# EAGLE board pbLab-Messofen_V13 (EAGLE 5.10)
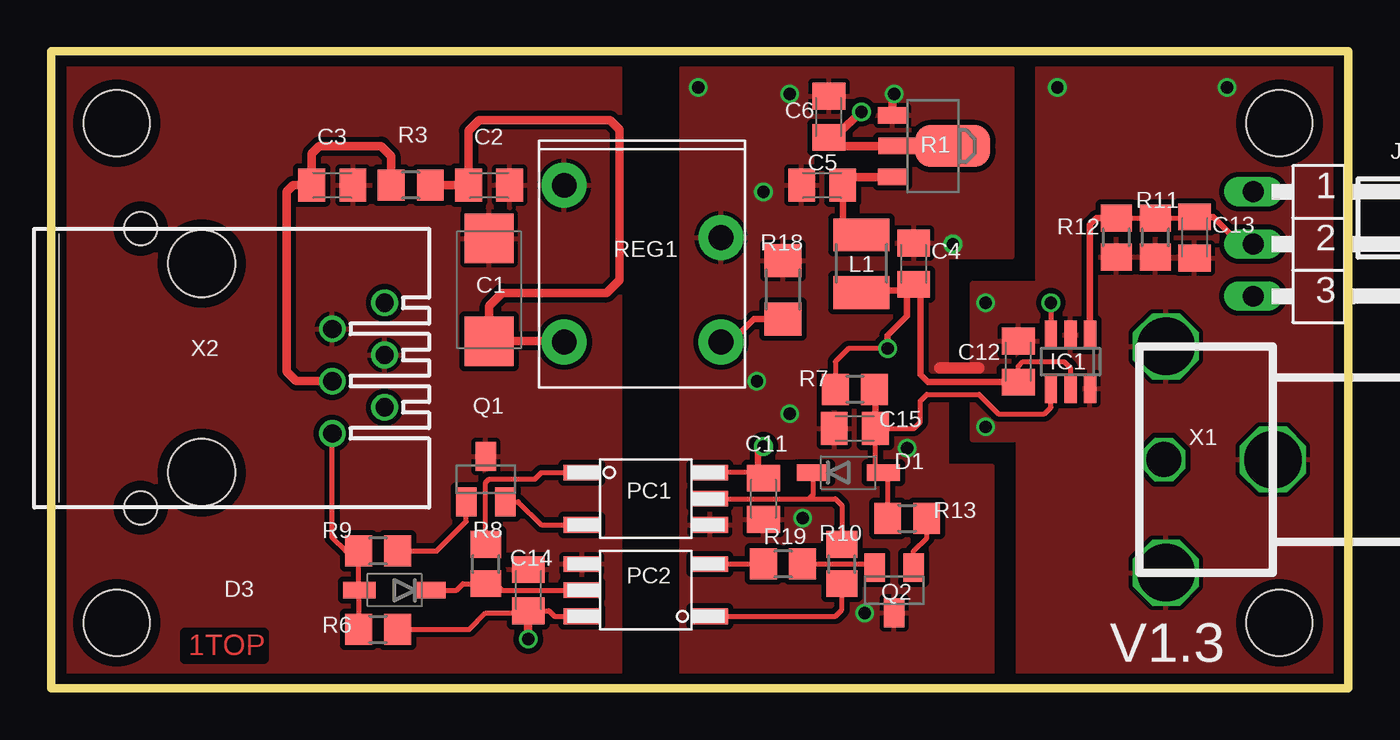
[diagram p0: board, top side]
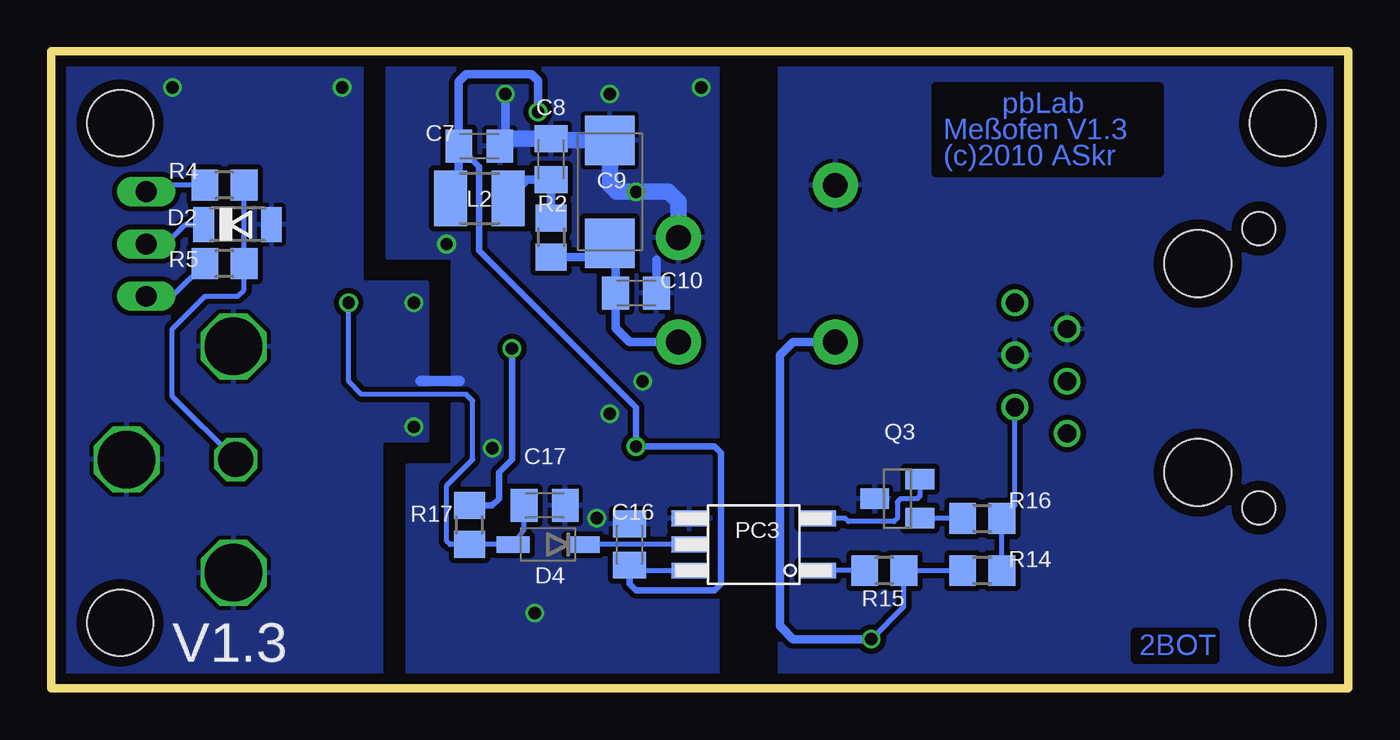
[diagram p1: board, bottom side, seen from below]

Size 63.02 x 30.96 mm. Coordinates in mm from the lower left corner, seen from the top.
Outline: 63.02,30.96 0,30.96 0,0 63.02,0 63.02,30.96
Copper layers (1*16): Top 0.035mm / dielectric 1.5mm / Bottom 0.035mm
Design rules "pcb-pool-2009": minimum track width 6mil, minimum drill 12mil, track to track 6mil, track to pad 6mil, pad to pad 6mil, via to via 6mil, smd to smd 6mil, copper to edge 20mil, drill to drill 8mil, minimum pad ring 8mil, minimum via ring 6mil, stop-mask expansion 3mil, vias tented up to drill 0mil, thermal gap 8mil
Holes 3.2 mm at 3.17,27.46 3.17,3.17 59.69,3.17 59.69,27.46
tRestrict: 8 lines
bRestrict: 8 lines

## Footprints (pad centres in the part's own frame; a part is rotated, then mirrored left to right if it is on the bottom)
SMC_C = smd 2.4 x 2.4: + -2.5,0; - 2.5,0
C0805K = smd 1.3 x 1.6: 1 -1,0; 2 1,0
SOD123 = smd 1.6 x 0.8: A 1.7,0; C -1.7,0
SOD80-R = smd 1 x 1.7: A 1.65,0; C -1.65,0
AKKI_SOT236W = smd 0.6 x 1.4: 1 -0.95,-1.303; 2 0,-1.303; 3 0.95,-1.303; 4 0.95,1.303; 5 0,1.303; 6 -0.95,1.303
1X03/90 = drill 1.016 long: 1 -2.54,-3.81; 2 0,-3.81; 3 2.54,-3.81
R1210 = smd 1.6 x 2.7: 1 -1.4,0; 2 1.4,0
AKKI_OPTOCOUP6SMD = smd 1.778 x 0.762: 1 -3.111,1.27; 3 -3.111,-1.27; 4 3.111,-1.27; 5 3.111,0; 6 3.111,1.27
SOT23-BEC = smd 1 x 1.4: B -0.95,-1.1; C 0,1.1; E 0.95,-1.1
SOT89 = smd 0.8 x 1.4: 1 -1.499,-1.981; 3 1.499,-1.981 | smd 0.8 x 1.9: 2 0,-1.727 | smd 2.032 x 3.65: 2@1 0,0.94
R0805 = smd 1.3 x 1.5: 1 -0.95,0; 2 0.95,0
R1206 = smd 1.6 x 1.803: 1 -1.422,0; 2 1.422,0
AKKI_AM1P-Z = drill 1.2 pad 2.184 round: 1 -2.54,-5.08; 4 5.08,-5.08; 5 5.08,2.54; 7 0,2.54
AKKI_CHINCH_CBP5 = drill 2.8 octagon: 1-1 5.2,-5.5; 1-2 5.2,5.5; 1-3 0,0 | drill 1.7 octagon: 2 5.3,0
AKKI_MEBP6-6G = drill 0.889 round: 1 -3.175,7.62; 2 -1.905,5.08; 3 -0.635,7.62; 4 0.635,5.08; 5 1.905,7.62; 6 3.175,5.08 | hole 3.251: -5.08,-1.27; 5.08,-1.27 | hole 1.6: -6.785,-4.24; 6.785,-4.24

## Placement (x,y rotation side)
C1  10u;16V  [SMC_C]  21.27,19.37 90 top
C2  100n  [C0805K]  21.27,24.45 0 top
C3  100n  [C0805K]  13.65,24.45 0 top
C4  1u  [C0805K]  41.91,20.64 90 top
C5  100n  [C0805K]  37.47,24.45 180 top
C6  10u  [C0805K]  37.78,27.78 90 top
C7  100n  [C0805K]  42.23,26.35 0 bottom
C8  100n  [C0805K]  38.73,25.72 90 bottom
C9  10u;16V  [SMC_C]  35.88,24.13 90 bottom
C10  100n  [C0805K]  34.61,19.21 0 bottom
C11  470n  [C0805K]  34.61,9.21 90 top
C12  100n  [C0805K]  46.99,15.88 90 top
C13  100n  [C0805K]  55.56,21.91 270 top
C14  470n  [C0805K]  23.18,4.76 90 top
C15  22p  [C0805K]  39.05,12.62 180 top
C16  470n  [C0805K]  34.92,6.99 270 bottom
C17  22p  [C0805K]  39.05,8.89 0 bottom
D1  LL103  [SOD123]  38.73,10.48 0 top
D2  4V7  [SOD80-R]  53.98,22.54 0 bottom
D3  LL103  [SOD123]  16.67,4.76 180 top
D4  LL103  [SOD123]  38.89,6.99 180 bottom
IC1  MCP3421  [AKKI_SOT236W]  49.53,15.88 180 top
JP1  [1X03/90]  62.23,21.59 270 top
L1  10u  [R1210]  39.37,20.64 90 top
L2  10u  [R1210]  42.23,23.81 0 bottom
PC1  TLP102  [AKKI_OPTOCOUP6SMD]  28.89,9.21 0 top
PC2  TLP102  [AKKI_OPTOCOUP6SMD]  28.89,4.76 180 top
PC3  TLP102  [AKKI_OPTOCOUP6SMD]  28.89,6.99 180 bottom
Q1  BC807-40  [SOT23-BEC]  21.11,10.16 0 top
Q2  BC807-40  [SOT23-BEC]  40.96,4.76 180 top
Q3  BC807-40  [SOT23-BEC]  21.91,9.21 90 bottom
R1  S817B33  [SOT89]  42.86,26.35 270 top
R2  10E  [R0805]  38.73,21.91 270 bottom
R3  1E  [R0805]  17.46,24.45 180 top
R4  1M2  [R0805]  54.61,24.45 180 bottom
R5  5k6  [R0805]  54.61,20.64 180 bottom
R6  120k  [R0805]  15.88,2.86 0 top
R7  120k  [R0805]  39.05,14.53 180 top
R8  470E  [R0805]  21.11,6.03 90 top
R9  5k6  [R0805]  15.88,6.67 180 top
R10  470E  [R0805]  38.42,6.03 90 top
R11  120k  [R0805]  53.66,21.91 90 top
R12  120k  [R0805]  51.75,21.91 90 top
R13  5k6  [R0805]  41.59,8.26 0 top
R14  120k  [R0805]  17.78,5.71 180 bottom
R15  680E  [R0805]  22.54,5.72 180 bottom
R16  5k6  [R0805]  17.78,8.26 0 bottom
R17  120k  [R0805]  42.7,7.94 90 bottom
R18  470E  [R1206]  35.56,19.37 270 top
R19  0E  [R0805]  35.56,6.03 180 top
REG1  AM1P-Z  [AKKI_AM1P-Z]  30,21.91 270 top
X1  CHINCH  [AKKI_CHINCH_CBP5]  59.37,11.11 180 top
X2  MEBP6-6G  [AKKI_MEBP6-6G]  8.57,15.56 270 top

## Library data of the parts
C1 C9 = rcl; SMDPAC: SMCC
C2-C8 C10-C17 R2-R17 R19 = rcl; SMDPAC: 0805
D1 D3 D4 = Akki; SMDPAC: SOD123
D2 = Akki; SMDPAC: SOD80
IC1 PC1-PC3 R1 REG1 X1 X2 = Akki
JP1 = pinhead
L1 L2 = Akki; SMDPAC: 1210
Q1-Q3 = transistor-pnp
R18 = rcl

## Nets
+3V3: C4.1 C12.1 IC1.5 L1.1 R7.2 R17.2
+5V: C3.1 R3.2 X2.4
+UB: C6.1 C7.1 C11.2 C16.2 L2.1 PC1.6 PC3.6 R1.2
+UB#2: C1.+ C2.1 C14.1 PC2.6 R3.1 R6.2 R14.2 R15.1 REG1.4
GNDI: C1.- C2.2 C3.2 C14.2 PC2.4 Q1.C Q3.C REG1.1 X2.2 X2.3
GNDO: C4.2 C5.2 C6.2 C7.2 C8.2 C9.- C10.2 C11.1 C12.2 C13.2 C15.2 C16.1 C17.2 D2.A IC1.2 IC1.6 PC1.4 PC3.4 Q2.C R1.1 R11.1 R12.1 R18.1 REG1.7 X1.1-1 X1.1-2 X1.1-3
N$1: PC3.3 Q3.E
N$2: C8.1 L2.2 R2.1
N$3: C9.+ C10.1 R2.2 R18.2 REG1.5
N$4: C5.1 L1.2 R1.3
N$5: PC3.1 R15.2
N$6: JP1.1 R4.2
N$7: Q3.B R16.1
N$8: R14.1 R16.2 X2.5
N$9: JP1.3 R5.2
N$10: C13.1 D2.C IC1.1 JP1.2 R11.2 R12.2
N$11: D4.C PC3.5
N$12: PC2.3 R19.2
N$13: R4.1 R5.1 X1.2
N$14: Q2.E R19.1
N$17: PC1.1 R8.2
N$18: D3.C PC2.5 R8.1
N$19: PC1.3 Q1.E
N$20: Q1.B R9.1
N$21: D3.A R6.1 R9.2 X2.6
N$22: PC2.1 R10.1
N$24: Q2.B R13.2
N$26: D1.C PC1.5 R10.2
SCL: C17.1 D4.A IC1.3 R17.1
SDA: C15.1 D1.A IC1.4 R7.1 R13.1

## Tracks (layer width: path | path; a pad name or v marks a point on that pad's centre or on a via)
+3V3  (via drill 0.6)
  Top 0.254: IC1.5 49.53,15.56 49.21,15.88 47.23,15.88 46.99,15.64 C12.1 | R7.2 38.1,15.88 38.73,16.51 v40.64,16.51
  Top 0.305: C12.1 42.59,14.88 42.23,15.24 42.23,19 C4.1 41.59,19.32 | v40.64,16.51 40.64,17.14 41.59,18.1 41.59,19.32 | 41.59,19.32 39.45,19.32 L1.1
  Bottom 0.305: v40.64,16.51 40.64,11.11 41.27,10.48 41.27,9.21 41.59,8.89 R17.2
+5V
  Top 0.406: X2.4 11.91,14.92 11.43,15.4 11.43,24.13 11.75,24.45 C3.1 | C3.1 | C3.1 12.65,25.99 13.02,26.35 16.03,26.35 16.51,25.88 R3.2
+UB  (via drill 0.6)
  Top 0.254: PC1.6 34.34,10.48 C11.2
  Top 0.305: 34.34,10.48 34.34,11.48 v34.61,11.75 | 38.21,26.94 C6.1
  Top 0.406: v39.37,28.02 38.21,26.94 | R1.2 38.37,26.35 C6.1
  Bottom 0.254: PC3.6 34.66,5.71 C16.2
  Bottom 0.305: C16.2 34.92,5.08 34.61,4.76 30.8,4.76 30.48,5.08 30.48,11.43 30.8,11.75 v34.61,11.75 34.61,13.65 42.23,21.27 42.23,25.35 C7.1
  Bottom 0.406: L2.1 43.23,24.21 C7.1 43.23,29.48 42.86,29.84 39.69,29.84 39.37,29.53 v39.37,28.02
+UB#2  (via drill 0.6)
  Top 0.254: PC2.6 24.45,3.49 24.18,3.76 C14.1 | C14.1 23.13,3.81 | R6.2 20.32,2.86 21.11,3.65 23.07,3.65 C14.1
  Top 0.406: REG1.4 24.88,16.87 C1.+ 21.27,18.57 21.91,19.21 26.99,19.21 27.62,19.84 27.62,27.15 27.15,27.62 20.8,27.62 20.27,27.1 C2.1 R3.1 | C14.1 v23.18,2.38
  Bottom 0.254: R14.2 R15.1 21.59,3.97 v23.18,2.38
  Bottom 0.406: REG1.4 26.99,16.83 27.62,16.19 27.62,3.02 26.99,2.38 v23.18,2.38
GNDI
  pour Top (isolate 0.254): 0.64,30.16 27.62,30.16 27.62,0.32 0.64,0.32
  pour Bottom (isolate 0.254): 0.64,30.16 27.62,30.16 27.62,0.32 0.64,0.32
GNDO  (via drill 0.6)
  Top 0.406: R1.1 40.88,28.82 v40.96,28.89 40.91,28.94 | C6.2 37.73,28.89
  Top 0.559: 45.09,15.56 43.18,15.56
  Bottom 0.406: C10.2 33.61,20.84 | v40.96,28.89 40.96,26.62 C7.2
  Bottom 0.508: 43.18,14.92 45.09,14.92
  Bottom 0.813: REG1.7 32.54,23.65 33.02,24.13 35.56,24.13 35.88,24.45 C9.- 38.65,26.63 C8.2 40.86,26.72 C7.2
  other vias: 43.81,21.59 48.9,29.21 57.15,29.21 45.4,12.7 45.4,18.73 31.43,29.21 35.88,28.89 34.61,24.13 35.88,13.34 34.29,14.92 36.51,8.26 39.53,3.65 41.59,11.67
  pour Top (isolate 0.254): 47.94,30.16 62.87,30.16 62.87,0.32 46.99,0.32 46.99,12.06 44.77,12.06 44.77,19.68 47.94,19.68
  pour Bottom (isolate 0.254): 47.94,30.16 62.87,30.16 62.87,0.32 46.99,0.32 46.99,12.06 44.77,12.06 44.77,19.68 47.94,19.68
  pour Top (isolate 0.254): 30.64,30.16 46.67,30.16 46.67,20.95 43.5,20.95 43.5,10.79 45.72,10.79 45.72,0.32 30.64,0.32
  pour Bottom (isolate 0.254): 30.64,30.16 46.67,30.16 46.67,20.95 43.5,20.95 43.5,10.79 45.72,10.79 45.72,0.32 30.64,0.32
N$1
  Bottom 0.254: Q3.E 20.81,9.36 20.95,9.21 21.75,9.21 21.91,9.05 21.91,8.26 22.07,8.1 24.29,8.1 24.45,8.26 PC3.3
N$2
  Bottom 0.406: R2.1 C8.1 39.92,24.72 L2.2
N$3
  Top 0.305: REG1.5 33.02,16.83 34.14,17.95 R18.2
  Bottom 0.406: R2.2 36.55,20.96 C9.+ 35.61,21.36 C10.1 35.61,17.51 34.92,16.83 REG1.5
N$4
  Top 0.305: C5.1 38.47,22.5 38.73,22.23 39.18,22.23 L1.2
  Top 0.406: R1.3 38.87,24.85 C5.1
N$5
  Bottom 0.254: R15.2 PC3.1 | PC3.1
N$6
  Bottom 0.254: R4.2 58.1,24.45 JP1.1
N$7
  Bottom 0.254: R16.1 Q3.B
N$8
  Bottom 0.254: R16.2 | R14.1 R16.2 | R14.1 | X2.5 16.19,8.89 R16.2
N$9
  Bottom 0.254: R5.2 57.15,19.05 JP1.3
N$10
  Top 0.254: C13.1 55.83,22.86 R11.2 R12.2 | IC1.1
  Top 0.305: C13.1 56.47,22.91 57.31,22.07 JP1.2 | IC1.1 50.48,22.54 50.8,22.86 R12.2
  Bottom 0.254: D2.C 56.52,22.54 57.15,21.91 JP1.2
N$11
  Bottom 0.254: PC3.5 D4.C
N$12
  Top 0.254: PC2.3 R19.2
N$13
  Bottom 0.254: X1.2 57.15,14.19 57.15,17.46 55.56,19.05 53.98,19.05 53.66,19.36 R5.1 R4.1
N$14
  Top 0.254: R19.1 39.84,6.03 Q2.E
N$17
  Top 0.254: R8.2 21.11,10 21.27,10.16 23.5,10.16 23.81,10.48 PC1.1
N$18
  Top 0.254: PC2.5 21.91,4.76 21.59,5.08 R8.1 20,5.08 19.68,4.76 D3.C
N$19
  Top 0.254: Q1.E 22.69,9.06 23.81,7.94 PC1.3
N$20
  Top 0.254: Q1.B 20.16,8.1 18.73,6.67 R9.1
N$21
  Top 0.254: X2.6 13.65,7.3 14.29,6.67 R9.2 14.93,4.81 D3.A 14.93,4.72 R6.1
N$22
  Top 0.254: PC2.1 38.1,3.49 38.42,3.81 R10.1
N$24
  Top 0.254: Q2.B 41.91,6.67 42.55,7.3 R13.2
N$26
  Top 0.254: PC1.5 36.83,9.21 | 36.83,9.21 38.1,9.21 38.42,8.89 R10.2 | D1.C 37.03,9.41 36.83,9.21
SCL  (via drill 0.6)
  Top 0.254: v48.58,18.73 IC1.3
  Bottom 0.254: C17.1 40.05,7.68 D4.A 42.86,6.99 R17.1 43.66,6.99 43.81,7.14 43.81,9.84 42.55,11.11 42.55,13.97 42.86,14.29 47.94,14.29 48.58,14.92 v48.58,18.73
SDA
  Top 0.254: D1.A 40.33,10.37 | D1.A 40.05,10.86 C15.1 41.91,12.62 42.23,12.94 42.23,13.97 42.55,14.29 45.09,14.29 46.04,13.34 48.26,13.34 48.58,13.65 IC1.4 | R13.1 40.64,10.27 D1.A
  Top 0.305: C15.1 40.05,14.24 R7.1

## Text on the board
Top: 1TOP
Bottom: pbLab | Meßofen V1.3 | (c)2010 ASkr | 2BOT
tPlace: 1 | 43V | 2 | 2V | 3 | V1.3
bPlace: V1.3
